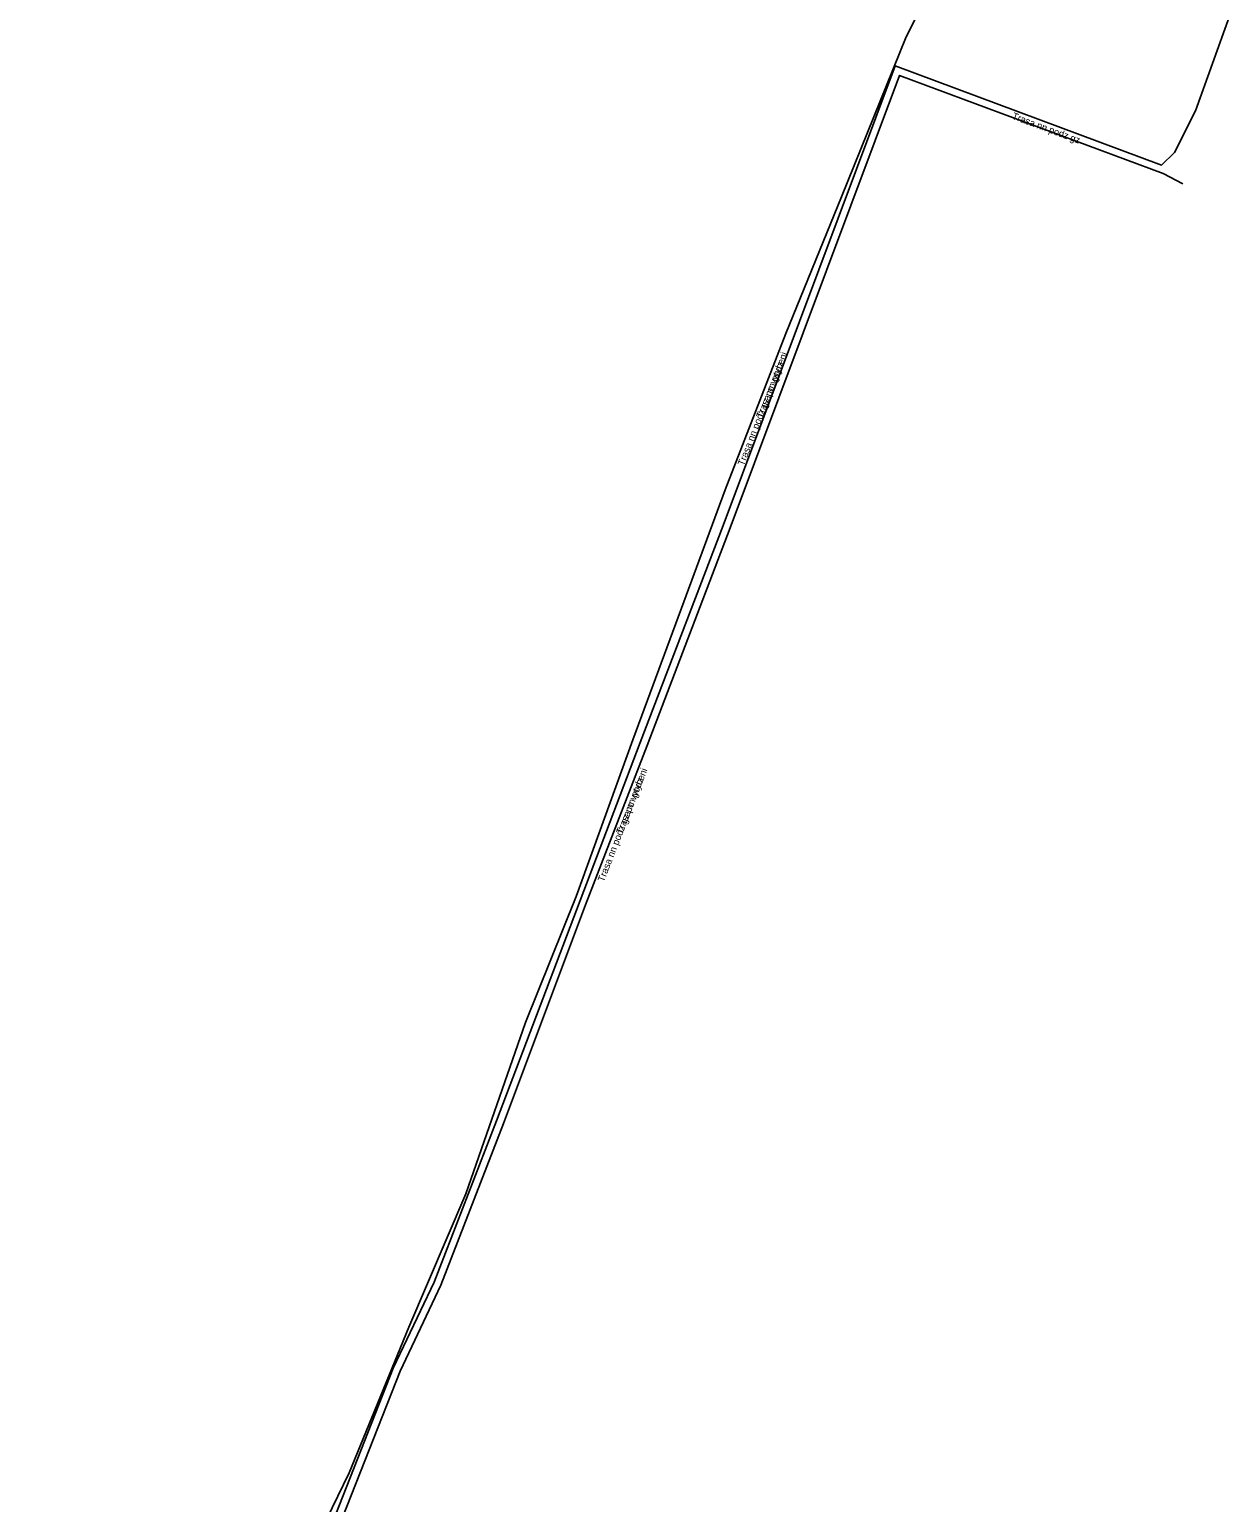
# Model space of a CAD drawing. Extents: x -528224 to -527720, y -1080003 to -1079672.
# Drawn here: x -527834.8 to -527748.5, y -1079896.6 to -1079790.6 of the extents above; entities that cross this region are included whole.
import ezdxf

# ---------------------------------------------------------------- set-up
doc = ezdxf.new("R2010")
doc.units = 0
doc.layers.add('Popiskový text - Ostatní atributy Trasy', color=7, linetype='Continuous')
doc.layers.add('Spojnice NN', color=7, linetype='Continuous')

msp = doc.modelspace()

# ---------------------------------------------------------------- linework, layer by layer
at = {"layer": 'Spojnice NN'}
for points in [[(-527768.79, -1079785.26), (-527771.74, -1079791.12), (-527776.4, -1079802.63), (-527780.4, -1079812.47), (-527784.78, -1079823.7), (-527788.33, -1079833.32), (-527791.41, -1079841.7), (-527795.5, -1079852.97), (-527799.14, -1079862.03), (-527803.45, -1079874.36), (-527807.54, -1079883.96), (-527811.84, -1079894.44), (-527814.69, -1079900.32)], [(-527768.79, -1079785.26), (-527771.74, -1079791.12), (-527776.4, -1079802.63), (-527780.4, -1079812.47), (-527784.78, -1079823.7), (-527788.33, -1079833.32), (-527791.41, -1079841.7), (-527795.5, -1079852.97), (-527799.14, -1079862.03), (-527803.45, -1079874.36), (-527807.54, -1079883.96), (-527811.84, -1079894.44), (-527814.69, -1079900.32)], [(-527834.85, -1079903.58), (-527819.81, -1079907.25), (-527814.79, -1079901.47), (-527812.8, -1079897.42), (-527808.66, -1079886.9), (-527805.73, -1079880.72), (-527801.23, -1079869.11), (-527790.88, -1079841.9), (-527784.91, -1079826.27), (-527772.54, -1079793.21), (-527753.38, -1079800.34), (-527752.44, -1079799.43), (-527750.93, -1079796.43), (-527748.47, -1079789.63)], [(-527751.84, -1079801.69), (-527753.24, -1079800.96), (-527772.22, -1079793.89), (-527784.41, -1079826.45), (-527790.38, -1079842.1), (-527794.83, -1079853.58), (-527800.73, -1079869.3), (-527805.23, -1079880.94), (-527808.17, -1079887.12), (-527812.31, -1079897.64), (-527814.34, -1079901.77), (-527819.63, -1079907.85), (-527827.33, -1079905.97)], [(-527751.84, -1079801.69), (-527753.24, -1079800.96), (-527772.22, -1079793.89), (-527784.41, -1079826.45), (-527790.38, -1079842.1), (-527794.83, -1079853.58), (-527800.73, -1079869.3), (-527805.23, -1079880.94), (-527808.17, -1079887.12), (-527812.31, -1079897.64), (-527814.34, -1079901.77), (-527819.63, -1079907.85), (-527827.33, -1079905.97)]]:
    msp.add_lwpolyline(points, dxfattribs=at)

# ---------------------------------------------------------------- texts
at = {"layer": 'Popiskový text - Ostatní atributy Trasy'}
for s, rotation, p in [('Trasa nn podz gz', 339.5797, (-527764.17, -1079797.01)), ('Trasa nn podz gz po vytyceni', 68.7057, (-527783.43, -1079822.02)), ('Trasa nn podz', 68.7057, (-527782.09, -1079818.59)), ('Trasa nn podz gz po vytyceni', 68.8273, (-527793.5, -1079851.96)), ('Trasa nn podz', 68.8273, (-527792.17, -1079848.52))]:
    msp.add_text(s, height=0.5, rotation=rotation, dxfattribs=at).set_placement(p)

doc.saveas('drawing.dxf')
